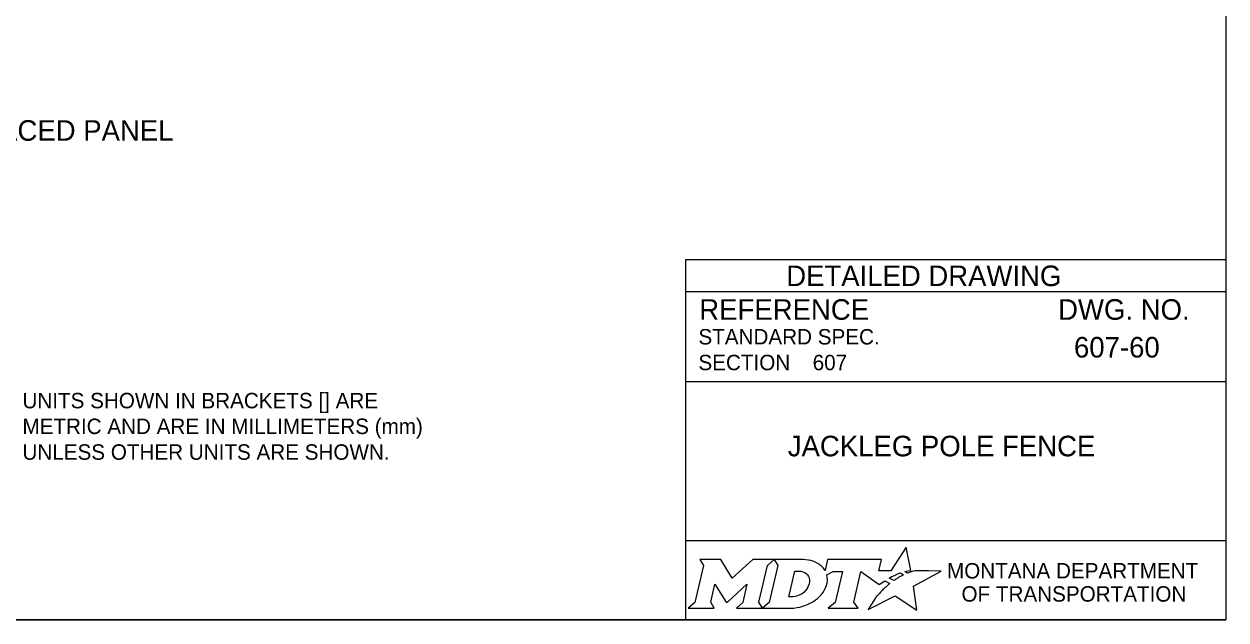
# Model space of a CAD drawing. Extents: x 49991.4 to 50021, y 49987.6 to 50011.4.
# Drawn here: x 50012.08 to 50016.75, y 49987.799 to 49990.115 of the extents above; entities that cross this region are included whole.
import ezdxf

# ---------------------------------------------------------------- set-up
doc = ezdxf.new("R2010")
doc.units = 0
for name, color, linetype in [('Default', 7, 'Continuous'), ('Level 1', 7, 'Continuous'), ('Level 2', 7, 'Continuous'), ('Level 3', 7, 'Continuous'), ('Level 5', 7, 'Continuous')]:
    doc.layers.add(name, color=color, linetype=linetype)

msp = doc.modelspace()

# ---------------------------------------------------------------- linework, layer by layer
at = {"layer": 'Default'}
for points in [[(50015.5126, 49987.9811), (50015.5023, 49987.9867), (50015.5139, 49987.9895), (50015.5255, 49987.9915), (50015.5081, 49988.0816), (50015.4486, 49987.9903), (50015.4013, 49987.9896), (50015.4116, 49988.0337), (50015.2024, 49988.0338), (50015.1923, 49987.9913), (50015.1865, 49987.9996)], [(50014.7056, 49988.0338), (50014.7197, 49988.0104), (50014.6862, 49987.8671), (50014.6605, 49987.8446), (50014.7621, 49987.8446), (50014.7486, 49987.8674), (50014.7648, 49987.9375), (50014.8085, 49987.8685), (50014.8138, 49987.8685), (50014.8889, 49987.938), (50014.8725, 49987.8669), (50014.8478, 49987.8449), (50014.9494, 49987.8449), (50014.9356, 49987.8682), (50014.9688, 49988.0106)], [(50014.9688, 49988.0106), (50014.9941, 49988.0338), (50014.9117, 49988.0338), (50014.8321, 49987.9608), (50014.7876, 49988.0335), (50014.7056, 49988.0338)], [(50015.1077, 49988.0338), (50014.9941, 49988.0338), (50015.0088, 49988.0109), (50014.9749, 49987.8671), (50014.9494, 49987.8449), (50015.06, 49987.8449)], [(50015.1317, 49987.9471), (50015.1305, 49987.939), (50015.1273, 49987.9297), (50015.1231, 49987.9215), (50015.1175, 49987.914), (50015.111, 49987.9071), (50015.1031, 49987.9008), (50015.0948, 49987.8961), (50015.0857, 49987.8922), (50015.0766, 49987.8899), (50015.0674, 49987.889), (50015.0515, 49987.889), (50015.0751, 49987.989), (50015.0911, 49987.989), (50015.0987, 49987.9884), (50015.1063, 49987.9865), (50015.1129, 49987.9835), (50015.119, 49987.9793), (50015.1238, 49987.9743), (50015.1275, 49987.9683), (50015.1302, 49987.9621), (50015.1318, 49987.9547), (50015.1318, 49987.9517), (50015.1317, 49987.9471)], [(50015.1991, 49987.9747), (50015.2237, 49987.9878), (50015.2606, 49987.9878), (50015.232, 49987.8673), (50015.2045, 49987.8446), (50015.3207, 49987.8446), (50015.3037, 49987.8675), (50015.3319, 49987.9877), (50015.4032, 49987.936), (50015.4243, 49987.9511), (50015.444, 49987.9402)], [(50015.3882, 49987.8843), (50015.3729, 49987.8599), (50015.3682, 49987.8524), (50015.3624, 49987.8438), (50015.3601, 49987.8395), (50015.4654, 49987.8926), (50015.5493, 49987.8375), (50015.5362, 49987.9302), (50015.6431, 49987.9886), (50015.5938, 49987.9894), (50015.5637, 49987.9898), (50015.5429, 49987.9901), (50015.5361, 49987.9886), (50015.5312, 49987.9874), (50015.5228, 49987.9851), (50015.5126, 49987.9811)], [(50015.4622, 49987.9535), (50015.4598, 49987.9518), (50015.4415, 49987.9614), (50015.4518, 49987.9671), (50015.4559, 49987.9693), (50015.4645, 49987.9733), (50015.4702, 49987.9759), (50015.4781, 49987.9789), (50015.4854, 49987.9816), (50015.4972, 49987.9742), (50015.4932, 49987.9721), (50015.4886, 49987.9696), (50015.4844, 49987.9674), (50015.4794, 49987.9645), (50015.4775, 49987.9634), (50015.4748, 49987.9618), (50015.4723, 49987.9604), (50015.47, 49987.9588), (50015.4674, 49987.957), (50015.4647, 49987.9552), (50015.4622, 49987.9535)], [(50015.1057, 49987.8522), (50015.1141, 49987.8548), (50015.1271, 49987.8602), (50015.1475, 49987.8712)], [(50015.4021, 49987.9004), (50015.4021, 49987.9004)]]:
    msp.add_lwpolyline(points, dxfattribs=at)
for centre, radius, start, end in [((50015.1308, 49987.9554), 0.0709, 339.5329, 15.8582), ((50015.0868, 49987.9727), 0.1183, 300.9103, 339.1383)]:
    msp.add_arc(centre, radius, start, end, dxfattribs=at)
for centre, major_axis, ratio, start_param, end_param in [((50015.1056, 49987.9864), (0.0834, -0.0037), 0.568097, 0.61298, 1.570796), ((50015.1612, 49987.9937), (0.0361, -0.0295), 0.469099, 1.225588, 1.570796), ((50015.4119, 49987.9106), (-0.0098, -0.0102), 0.016458, 3.141593, 6.279097), ((50015.4329, 49987.9305), (-0.0112, -0.0097), 0.021651, 3.157348, 6.283185), ((50015.3952, 49987.8923), (-0.00694, -0.00806), 0.008222, 0, 3.137361), ((50015.0603, 49987.9932), (0, 0.1484), 0.987302, 3.139398, 3.456847)]:
    msp.add_ellipse(centre, major_axis=major_axis, ratio=ratio, start_param=start_param, end_param=end_param, dxfattribs=at)
at = {"layer": 'Level 1'}
msp.add_lwpolyline([(49999.3835, 49998.9992), (50016.7501, 49998.9992), (50016.7501, 49987.7988), (49999.3835, 49987.7988)], close=True, dxfattribs=at)
at = {"layer": 'Level 3'}
msp.add_line((49999.3835, 49987.7988), (50016.7501, 49987.7988), dxfattribs=at)
at = {"layer": 'Level 5'}
for p, q in [((50016.7501, 49989.1988), (50014.6501, 49989.1988)), ((50014.6501, 49989.1988), (50014.6501, 49987.7988)), ((50016.7501, 49989.0738), (50014.6501, 49989.0738)), ((50016.3862, 49988.8587), (50016.3862, 49988.8587)), ((50015.1444, 49988.7993), (50015.1444, 49988.7993)), ((50016.7501, 49988.7238), (50014.6501, 49988.7238)), ((50015.7001, 49988.4747), (50015.7001, 49988.4747)), ((50016.7501, 49988.1057), (50014.6501, 49988.1057))]:
    msp.add_line(p, q, dxfattribs=at)

# ---------------------------------------------------------------- texts
at = {"layer": 'Default'}
for s, p in [('MONTANA DEPARTMENT', (50015.6663, 49987.96)), ('OF TRANSPORTATION', (50015.7225, 49987.87))]:
    msp.add_text(s, height=0.06, dxfattribs=at).set_placement(p)
at = {"layer": 'Level 2'}
for s, height, p in [('BRACED PANEL', 0.08, (50011.8347, 49989.6612)), ('607-60', 0.08, (50016.1596, 49988.8187)), ('607', 0.06, (50015.1444, 49988.7693)), ('UNITS SHOWN IN BRACKETS [] ARE ', 0.06, (50012.074, 49988.6214)), ('METRIC AND ARE IN MILLIMETERS (mm) ', 0.06, (50012.074, 49988.5214)), ('UNLESS OTHER UNITS ARE SHOWN.', 0.06, (50012.074, 49988.4214)), ('JACKLEG POLE FENCE', 0.08, (50015.0476, 49988.4347))]:
    msp.add_text(s, height=height, dxfattribs=at).set_placement(p)
at = {"layer": 'Level 5'}
for s, height, p in [('DETAILED DRAWING', 0.0799, (50015.0418, 49989.0963)), ('REFERENCE', 0.08, (50014.7037, 49988.9654)), ('DWG. NO.', 0.08, (50016.0979, 49988.9654)), ('STANDARD SPEC.', 0.06, (50014.7004, 49988.8694)), ('SECTION', 0.06, (50014.7004, 49988.7694))]:
    msp.add_text(s, height=height, dxfattribs=at).set_placement(p)

doc.saveas('drawing.dxf')
